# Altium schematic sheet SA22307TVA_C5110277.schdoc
size 127 x 101 mm
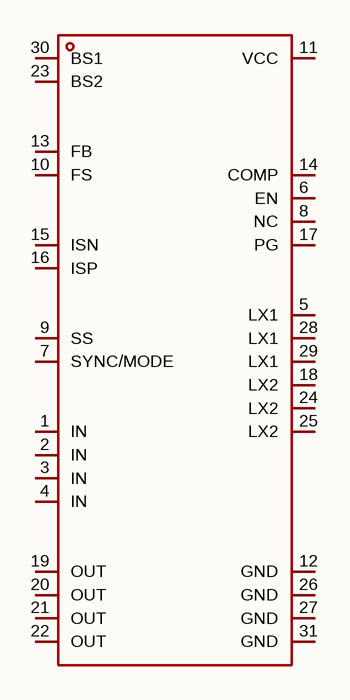
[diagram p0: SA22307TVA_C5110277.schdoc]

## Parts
U?  sa22307tva_c5110277  [QFN-30_L5.0-W5.0-P0.45-TL-EP_SA22307TVA]  (value not drawn)

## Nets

Not connected (* = marked no-connect by the designer): U? 1(IN) 2(IN) 3(IN) 4(IN) 5(LX1) 6(EN) 7(SYNC/MODE) 8(NC) 9(SS) 10(FS) 11(VCC) 12(GND) 13(FB) 14(COMP) 15(ISN) 16(ISP) 17(PG) 18(LX2) 19(OUT) 20(OUT) 21(OUT) 22(OUT) 23(BS2) 24(LX2) 25(LX2) 26(GND) 27(GND) 28(LX1) 29(LX1) 30(BS1) 31(GND)

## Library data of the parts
U? = sa22307tva_c5110277: 功能类型:升降压型;工作电压:4V~36V;输出电压:3V~20V;输出电流:-;输出类型:可调;; Manufacturer: Silergy(矽力杰); AddInBom: yes; Function: 升降压型; Voltage - Supply: 4V~36V; Output Voltage: 3V~20V; Frequency - Switching: 200kHz~600kHz; Synchronous Rectifier: 是; Number of Outputs: 1; Topology: 降压-升压式; Quiescent Current: 200uA; Switch tube (built-in/external): 内置; Output Type: 可调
